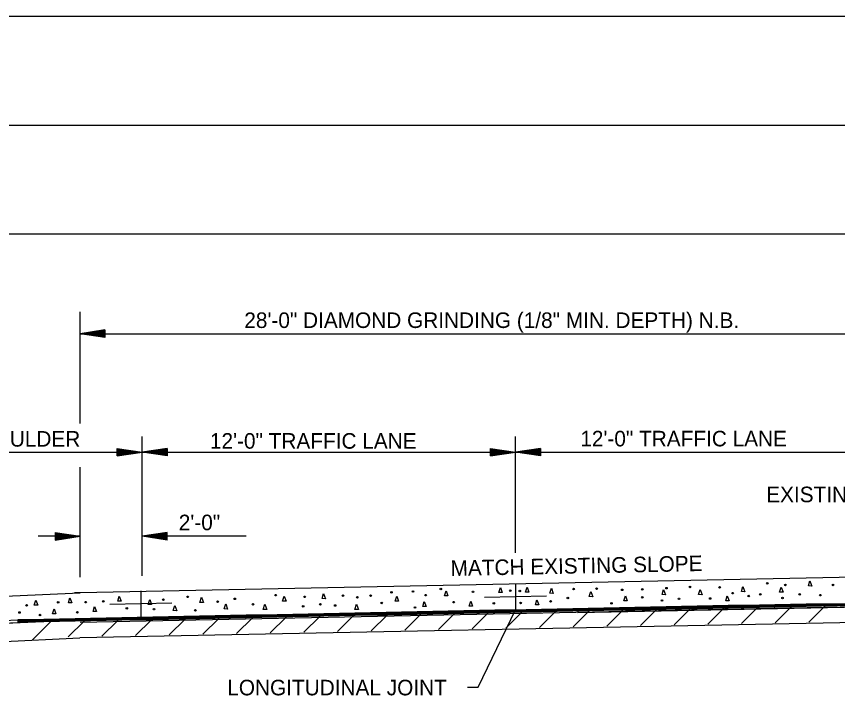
# Model space of a CAD drawing. Extents: x 60325 to 61047, y 53669 to 53767.
# Drawn here: x 60530.5 to 60556.9, y 53690.3 to 53712.12 of the extents above; entities that cross this region are included whole.
import ezdxf

# ---------------------------------------------------------------- set-up
doc = ezdxf.new("R2010")
doc.units = 0
doc.layers.add('R_Border', color=7, linetype='Continuous')
doc.layers.add('R_Border Prem', color=7, linetype='Continuous')

msp = doc.modelspace()

# ---------------------------------------------------------------- linework, layer by layer
at = {"layer": 'R_Border'}
for p, q in [((60532.545, 53699.038), (60532.545, 53702.635)), ((60533.345, 53702.049), (60532.545, 53701.929)), ((60533.345, 53701.809), (60532.545, 53701.929)), ((60532.545, 53701.929), (60560.545, 53701.929)), ((60533.345, 53702.029), (60532.679, 53701.929)), ((60533.345, 53701.829), (60532.679, 53701.929)), ((60533.345, 53702.009), (60532.816, 53701.929)), ((60533.345, 53701.85), (60532.816, 53701.929)), ((60533.345, 53701.989), (60532.95, 53701.929)), ((60533.345, 53701.87), (60532.95, 53701.929)), ((60533.345, 53701.968), (60533.085, 53701.929)), ((60533.345, 53701.89), (60533.085, 53701.929)), ((60533.345, 53701.948), (60533.219, 53701.929)), ((60533.345, 53701.911), (60533.219, 53701.929)), ((60533.345, 53702.049), (60533.345, 53701.809)), ((60534.545, 53696.332), (60534.545, 53698.624)), ((60546.545, 53694.884), (60546.545, 53698.624)), ((60535.345, 53698.244), (60534.545, 53698.124)), ((60535.345, 53698.004), (60534.545, 53698.124)), ((60534.545, 53698.124), (60546.545, 53698.124)), ((60535.345, 53698.224), (60534.679, 53698.124)), ((60535.345, 53698.024), (60534.679, 53698.124)), ((60535.345, 53698.204), (60534.816, 53698.124)), ((60535.345, 53698.045), (60534.816, 53698.124)), ((60535.345, 53698.184), (60534.95, 53698.124)), ((60535.345, 53698.065), (60534.95, 53698.124)), ((60535.345, 53698.163), (60535.085, 53698.124)), ((60535.345, 53698.085), (60535.085, 53698.124)), ((60535.345, 53698.143), (60535.219, 53698.124)), ((60535.345, 53698.106), (60535.219, 53698.124)), ((60535.345, 53698.244), (60535.345, 53698.004)), ((60545.745, 53698.244), (60546.545, 53698.124)), ((60545.745, 53698.004), (60545.745, 53698.244)), ((60545.745, 53698.224), (60546.412, 53698.124)), ((60545.745, 53698.204), (60546.274, 53698.124)), ((60545.745, 53698.184), (60546.141, 53698.124)), ((60545.745, 53698.164), (60546.005, 53698.124)), ((60545.745, 53698.143), (60545.872, 53698.124)), ((60545.745, 53698.004), (60546.545, 53698.124)), ((60545.745, 53698.086), (60546.005, 53698.124)), ((60545.745, 53698.045), (60546.274, 53698.124)), ((60545.745, 53698.024), (60546.412, 53698.124)), ((60545.745, 53698.065), (60546.141, 53698.124)), ((60545.745, 53698.106), (60545.872, 53698.124)), ((60547.345, 53698.244), (60546.545, 53698.124)), ((60546.545, 53698.124), (60558.545, 53698.124)), ((60547.345, 53698.004), (60546.545, 53698.124)), ((60547.345, 53698.224), (60546.679, 53698.124)), ((60547.345, 53698.024), (60546.679, 53698.124)), ((60547.345, 53698.204), (60546.816, 53698.124)), ((60547.345, 53698.045), (60546.816, 53698.124)), ((60547.345, 53698.184), (60546.95, 53698.124)), ((60547.345, 53698.065), (60546.95, 53698.124)), ((60547.345, 53698.163), (60547.085, 53698.124)), ((60547.345, 53698.085), (60547.085, 53698.124)), ((60547.345, 53698.143), (60547.219, 53698.124)), ((60547.345, 53698.106), (60547.219, 53698.124)), ((60547.345, 53698.244), (60547.345, 53698.004)), ((60532.545, 53694.104), (60532.545, 53697.643)), ((60534.545, 53694.144), (60534.545, 53696.332)), ((60531.745, 53695.538), (60532.545, 53695.418)), ((60531.745, 53695.538), (60531.745, 53695.298)), ((60531.745, 53695.518), (60532.412, 53695.418)), ((60531.745, 53695.498), (60532.274, 53695.418)), ((60531.745, 53695.478), (60532.141, 53695.418)), ((60535.345, 53695.538), (60534.545, 53695.418)), ((60535.345, 53695.518), (60534.679, 53695.418)), ((60535.345, 53695.498), (60534.816, 53695.418)), ((60535.345, 53695.478), (60534.95, 53695.418)), ((60535.345, 53695.298), (60535.345, 53695.538)), ((60532.545, 53695.418), (60531.203, 53695.418)), ((60531.745, 53695.457), (60532.005, 53695.418)), ((60531.745, 53695.437), (60531.872, 53695.418)), ((60531.745, 53695.298), (60532.545, 53695.418)), ((60531.745, 53695.379), (60532.005, 53695.418)), ((60531.745, 53695.339), (60532.274, 53695.418)), ((60531.745, 53695.318), (60532.412, 53695.418)), ((60531.745, 53695.359), (60532.141, 53695.418)), ((60531.745, 53695.4), (60531.872, 53695.418)), ((60537.892, 53695.418), (60534.545, 53695.418)), ((60535.345, 53695.298), (60534.545, 53695.418)), ((60535.345, 53695.318), (60534.679, 53695.418)), ((60535.345, 53695.339), (60534.816, 53695.418)), ((60535.345, 53695.359), (60534.95, 53695.418)), ((60535.345, 53695.458), (60535.085, 53695.418)), ((60535.345, 53695.38), (60535.085, 53695.418)), ((60535.345, 53695.437), (60535.219, 53695.418)), ((60535.345, 53695.4), (60535.219, 53695.418)), ((60534.501, 53693.662), (60534.501, 53692.829)), ((60546.545, 53693.884), (60546.545, 53693.051)), ((60546.545, 53693.468), (60545.545, 53693.448)), ((60547.545, 53693.488), (60546.545, 53693.468)), ((60534.501, 53693.246), (60533.501, 53693.226)), ((60535.5, 53693.266), (60534.501, 53693.246)), ((60545.344, 53690.571), (60546.545, 53693.051)), ((60544.997, 53690.571), (60545.344, 53690.571))]:
    msp.add_line(p, q, dxfattribs=at)
msp.add_lwpolyline([(60560.556, 53694.161), (60558.545, 53694.124), (60532.545, 53693.604)], dxfattribs=at)
at = {"layer": 'R_Border Prem'}
for p, q in [((60618.545, 53712.124), (60524.545, 53712.124)), ((60619.713, 53708.624), (60522.149, 53708.624)), ((60619.713, 53705.124), (60522.149, 53705.124)), ((60532.545, 53699.374), (60532.545, 53702.635)), ((60525.541, 53698.124), (60534.545, 53698.124)), ((60533.745, 53698.244), (60534.545, 53698.124)), ((60533.745, 53698.004), (60533.745, 53698.244)), ((60533.745, 53698.224), (60534.412, 53698.124)), ((60533.745, 53698.204), (60534.274, 53698.124)), ((60533.745, 53698.184), (60534.141, 53698.124)), ((60533.745, 53698.164), (60534.005, 53698.124)), ((60533.745, 53698.143), (60533.872, 53698.124)), ((60533.745, 53698.004), (60534.545, 53698.124)), ((60533.745, 53698.086), (60534.005, 53698.124)), ((60533.745, 53698.045), (60534.274, 53698.124)), ((60533.745, 53698.024), (60534.412, 53698.124)), ((60533.745, 53698.065), (60534.141, 53698.124)), ((60533.745, 53698.106), (60533.872, 53698.124)), ((60525.541, 53693.284), (60532.545, 53693.604)), ((60532.545, 53693.597), (60532.373, 53693.597)), ((60571.545, 53693.511), (60532.545, 53692.731)), ((60571.545, 53693.431), (60532.545, 53692.651)), ((60552.886, 53693.098), (60548.885, 53693.098)), ((60553.386, 53693.108), (60549.385, 53693.108)), ((60553.886, 53693.118), (60549.885, 53693.118)), ((60554.386, 53693.128), (60550.385, 53693.128)), ((60554.886, 53693.138), (60550.885, 53693.138)), ((60555.386, 53693.148), (60551.385, 53693.148)), ((60555.886, 53693.158), (60551.885, 53693.158)), ((60556.386, 53693.168), (60552.385, 53693.168)), ((60553.24, 53693.105), (60552.73, 53692.595)), ((60556.886, 53693.178), (60552.885, 53693.178)), ((60557.386, 53693.188), (60553.385, 53693.188)), ((60554.323, 53693.127), (60553.812, 53692.616)), ((60557.886, 53693.198), (60553.885, 53693.198)), ((60558.386, 53693.208), (60554.385, 53693.208)), ((60558.886, 53693.218), (60554.885, 53693.218)), ((60555.405, 53693.148), (60554.895, 53692.638)), ((60559.386, 53693.228), (60555.385, 53693.228)), ((60559.886, 53693.238), (60555.885, 53693.238)), ((60556.487, 53693.17), (60555.977, 53692.66)), ((60571.545, 53692.931), (60532.542, 53692.151)), ((60539.886, 53692.838), (60535.885, 53692.838)), ((60540.386, 53692.848), (60536.385, 53692.848)), ((60540.886, 53692.858), (60536.885, 53692.858)), ((60541.386, 53692.868), (60537.385, 53692.868)), ((60541.886, 53692.878), (60537.885, 53692.878)), ((60542.386, 53692.888), (60538.385, 53692.888)), ((60542.886, 53692.898), (60538.885, 53692.898)), ((60543.386, 53692.908), (60539.385, 53692.908)), ((60540.253, 53692.845), (60539.742, 53692.335)), ((60543.886, 53692.918), (60539.885, 53692.918)), ((60544.386, 53692.928), (60540.385, 53692.928)), ((60541.335, 53692.867), (60540.825, 53692.356)), ((60544.886, 53692.938), (60540.885, 53692.938)), ((60545.386, 53692.948), (60541.385, 53692.948)), ((60545.886, 53692.958), (60541.885, 53692.958)), ((60542.417, 53692.888), (60541.907, 53692.378)), ((60546.386, 53692.968), (60542.385, 53692.968)), ((60546.886, 53692.978), (60542.885, 53692.978)), ((60543.5, 53692.91), (60542.989, 53692.4)), ((60547.386, 53692.988), (60543.385, 53692.988)), ((60547.886, 53692.998), (60543.885, 53692.998)), ((60544.582, 53692.932), (60544.072, 53692.421)), ((60548.386, 53693.008), (60544.385, 53693.008)), ((60548.886, 53693.018), (60544.885, 53693.018)), ((60545.664, 53692.953), (60545.154, 53692.443)), ((60549.386, 53693.028), (60545.385, 53693.028)), ((60549.886, 53693.038), (60545.885, 53693.038)), ((60546.746, 53692.975), (60546.236, 53692.465)), ((60550.386, 53693.048), (60546.385, 53693.048)), ((60550.886, 53693.058), (60546.885, 53693.058)), ((60547.829, 53692.997), (60547.318, 53692.486)), ((60551.386, 53693.068), (60547.385, 53693.068)), ((60551.886, 53693.078), (60547.885, 53693.078)), ((60552.386, 53693.088), (60548.385, 53693.088)), ((60548.911, 53693.018), (60548.401, 53692.508)), ((60549.993, 53693.04), (60549.483, 53692.53)), ((60551.076, 53693.062), (60550.565, 53692.551)), ((60552.158, 53693.083), (60551.648, 53692.573)), ((60524.545, 53692.366), (60532.585, 53692.733)), ((60534.386, 53692.728), (60530.545, 53692.728)), ((60533.886, 53692.718), (60530.545, 53692.718)), ((60533.386, 53692.708), (60530.545, 53692.708)), ((60532.886, 53692.698), (60530.545, 53692.698)), ((60532.386, 53692.688), (60530.545, 53692.688)), ((60531.886, 53692.678), (60530.545, 53692.678)), ((60531.386, 53692.668), (60530.545, 53692.668)), ((60530.886, 53692.658), (60530.545, 53692.658)), ((60530.576, 53692.652), (60530.545, 53692.652)), ((60534.886, 53692.738), (60530.885, 53692.738)), ((60531.594, 53692.672), (60531.003, 53692.081)), ((60535.386, 53692.748), (60531.385, 53692.748)), ((60535.886, 53692.758), (60531.885, 53692.758)), ((60532.676, 53692.694), (60532.166, 53692.183)), ((60536.386, 53692.768), (60532.385, 53692.768)), ((60536.886, 53692.778), (60532.885, 53692.778)), ((60533.759, 53692.715), (60533.248, 53692.205)), ((60537.386, 53692.788), (60533.385, 53692.788)), ((60537.886, 53692.798), (60533.885, 53692.798)), ((60534.841, 53692.737), (60534.331, 53692.227)), ((60538.386, 53692.808), (60534.385, 53692.808)), ((60538.886, 53692.818), (60534.885, 53692.818)), ((60539.386, 53692.828), (60535.385, 53692.828)), ((60535.923, 53692.759), (60535.413, 53692.248)), ((60537.006, 53692.78), (60536.495, 53692.27)), ((60538.088, 53692.802), (60537.578, 53692.292)), ((60539.17, 53692.823), (60538.66, 53692.313)), ((60520.747, 53691.612), (60532.542, 53692.151))]:
    msp.add_line(p, q, dxfattribs=at)
for points in [[(60556.011, 53693.985), (60556.071, 53693.819), (60555.961, 53693.823), (60556.011, 53693.985)], [(60544.315, 53693.668), (60544.375, 53693.502), (60544.265, 53693.506), (60544.315, 53693.668)], [(60546.059, 53693.773), (60546.12, 53693.607), (60546.01, 53693.612), (60546.059, 53693.773)], [(60546.918, 53693.787), (60546.979, 53693.621), (60546.869, 53693.625), (60546.918, 53693.787)], [(60547.698, 53693.747), (60547.758, 53693.581), (60547.648, 53693.586), (60547.698, 53693.747)], [(60548.967, 53693.641), (60549.027, 53693.475), (60548.917, 53693.48), (60548.967, 53693.641)], [(60551.306, 53693.707), (60551.366, 53693.541), (60551.256, 53693.546), (60551.306, 53693.707)], [(60552.482, 53693.707), (60552.543, 53693.541), (60552.433, 53693.546), (60552.482, 53693.707)], [(60553.856, 53693.8), (60553.917, 53693.634), (60553.807, 53693.638), (60553.856, 53693.8)], [(60555.086, 53693.787), (60555.146, 53693.621), (60555.036, 53693.625), (60555.086, 53693.787)], [(60531.125, 53693.367), (60531.185, 53693.201), (60531.075, 53693.205), (60531.125, 53693.367)], [(60532.221, 53693.444), (60532.282, 53693.278), (60532.172, 53693.282), (60532.221, 53693.444)], [(60533.808, 53693.496), (60533.869, 53693.33), (60533.759, 53693.334), (60533.808, 53693.496)], [(60534.786, 53693.39), (60534.846, 53693.224), (60534.736, 53693.229), (60534.786, 53693.39)], [(60536.451, 53693.456), (60536.512, 53693.29), (60536.402, 53693.295), (60536.451, 53693.456)], [(60539.108, 53693.496), (60539.168, 53693.33), (60539.058, 53693.334), (60539.108, 53693.496)], [(60540.376, 53693.575), (60540.437, 53693.409), (60540.327, 53693.414), (60540.376, 53693.575)], [(60542.729, 53693.496), (60542.789, 53693.33), (60542.679, 53693.334), (60542.729, 53693.496)], [(60547.235, 53693.377), (60547.296, 53693.211), (60547.186, 53693.215), (60547.235, 53693.377)], [(60550.077, 53693.509), (60550.137, 53693.343), (60550.027, 53693.348), (60550.077, 53693.509)], [(60553.354, 53693.509), (60553.415, 53693.343), (60553.305, 53693.348), (60553.354, 53693.509)], [(60533.015, 53693.166), (60533.076, 53693), (60532.966, 53693.004), (60533.015, 53693.166)], [(60535.592, 53693.192), (60535.653, 53693.026), (60535.543, 53693.03), (60535.592, 53693.192)], [(60537.231, 53693.245), (60537.291, 53693.079), (60537.181, 53693.083), (60537.231, 53693.245)], [(60538.486, 53693.232), (60538.547, 53693.066), (60538.437, 53693.07), (60538.486, 53693.232)], [(60541.434, 53693.232), (60541.494, 53693.066), (60541.384, 53693.07), (60541.434, 53693.232)], [(60543.614, 53693.324), (60543.675, 53693.158), (60543.565, 53693.163), (60543.614, 53693.324)], [(60545.108, 53693.337), (60545.168, 53693.171), (60545.058, 53693.176), (60545.108, 53693.337)], [(60531.712, 53693.088), (60531.772, 53692.922), (60531.662, 53692.927), (60531.712, 53693.088)]]:
    msp.add_lwpolyline(points, dxfattribs=at)
for points in [[(60571.545, 53693.511), (60548.545, 53693.051), (60548.545, 53692.971), (60571.545, 53693.431)], [(60530.547, 53692.734), (60530.547, 53692.64), (60524.545, 53692.366), (60524.545, 53692.452)]]:
    msp.add_lwpolyline(points, close=True, dxfattribs=at)
for centre in [(60554.639, 53693.908), (60542.56, 53693.617), (60543.247, 53693.644), (60544.146, 53693.723), (60545.176, 53693.631), (60546.379, 53693.67), (60546.683, 53693.657), (60548.414, 53693.723), (60549.154, 53693.736), (60549.974, 53693.697), (60550.621, 53693.71), (60551.401, 53693.749), (60552.154, 53693.789), (60553.106, 53693.776), (60555.22, 53693.855), (60556.754, 53693.855), (60535.225, 53693.379), (60536.005, 53693.472), (60537.524, 53693.406), (60538.833, 53693.525), (60539.771, 53693.472), (60541, 53693.512), (60541.463, 53693.459), (60541.886, 53693.512), (60543.657, 53693.525), (60548.229, 53693.432), (60550.621, 53693.459), (60551.256, 53693.353), (60551.798, 53693.406), (60552.802, 53693.419), (60553.529, 53693.591), (60554.044, 53693.498), (60554.414, 53693.551), (60555.128, 53693.432), (60555.683, 53693.551), (60556.344, 53693.525), (60530.828, 53693.198), (60531.843, 53693.295), (60532.727, 53693.3), (60533.295, 53693.327), (60534.049, 53693.102), (60534.921, 53693.075), (60536.969, 53693.313), (60538.106, 53693.234), (60539.718, 53693.168), (60540.273, 53693.234), (60540.749, 53693.194), (60542.243, 53693.274), (60543.313, 53693.128), (60544.555, 53693.3), (60545.85, 53693.26), (60546.709, 53693.274), (60547.674, 53693.327), (60549.63, 53693.26), (60530.599, 53692.968), (60531.261, 53692.888), (60532.461, 53692.977), (60536.256, 53693.036)]:
    msp.add_circle(centre, 0.025, dxfattribs=at)

# ---------------------------------------------------------------- texts
at = {"layer": 'R_Border'}
for s, p in [('28\'-0" DIAMOND GRINDING (1/8" MIN. DEPTH) N.B.', (60537.827, 53702.112)), ('12\'-0" TRAFFIC LANE', (60536.722, 53698.233)), ('12\'-0" TRAFFIC LANE', (60548.628, 53698.307)), ('2\'-0"', (60535.72, 53695.612)), ('LONGITUDINAL JOINT', (60537.279, 53690.306))]:
    msp.add_text(s, height=0.5, dxfattribs=at).set_placement(p)
msp.add_text('MATCH EXISTING SLOPE', height=0.5, rotation=1.1458, dxfattribs=at).set_placement((60544.463, 53694.14))
at = {"layer": 'R_Border Prem'}
for s, p in [('10\'-0" SHOULDER', (60526.95, 53698.299)), ('EXISTING CONCRETE BARRIER WALL', (60554.605, 53696.512))]:
    msp.add_text(s, height=0.5, dxfattribs=at).set_placement(p)

doc.saveas('drawing.dxf')
